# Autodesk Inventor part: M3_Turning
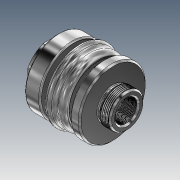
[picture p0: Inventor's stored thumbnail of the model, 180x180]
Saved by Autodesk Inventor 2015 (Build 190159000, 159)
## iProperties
Created: 2015-04
Part Number: M3_Turning
Material: Alumínio 6061
Document SubType Name: Modeling
Designer: Andrew Almeida
Density: 2.7 g/cm^3
Appearance: Alumínio - Plano
Title: C:/Users/Andrew Almeida/Documents/Projeto WS2015/WS2015 CAD Data ANLAS/06/#06 - CNC Turning/01 - 3D Models/M3_Turning.stp
Creation Date: 2015-04-23
Sending System: Autodesk Translation Framework v4.0.0.5211
Preprocessor: ST-DEVELOPER v16.1
Author: Andrew Almeida
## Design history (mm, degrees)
node "M3_Turning1"
feature "Rosca1" dims "d0" = 10, "d1" = 0
feature "Rosca2" dims "d2" = 10, "d3" = 0
sketch "Esboço2"
  geometry: L1 (23, 0)-(23, 12); L2 (23, 12)-(21.517, 12); L3 (21.517, 12)-(21.517, 0); L4 (21.517, 0)-(23, 0); L5 (0, -22.217)-(0, 118.036) reference
  constraints: 8 end point
revolve "Revolução1" sketch "Esboço2" stored, may be unused: angle "d13" = 0 deg
sketch "Esboço3"
  geometry: L1 (23, 0)-(23, 12); L2 (23, 12)-(21.517, 12); L3 (21.517, 12)-(21.517, 0); L4 (21.517, 0)-(23, 0); L5 (0, -22.217)-(0, 118.036) reference
  constraints: 8 end point
revolve "Revolução2" sketch "Esboço3" stored, may be unused: angle "d14" = 0 deg
sketch "Esboço1"
  geometry: L1 (-1.167, -21.618)-(-1, -21.618); L2 (0.167, -22.899)-(0, -23.219); L3 (-2, -23.219)-(-2.167, -22.899); L4 (-0.833, -21.618)-(-1, -21.298); L5 (-1, -21.298)-(-1.167, -21.618); L6 (-2, -23.219)-(-1.833, -22.899); L7 (-0.833, -21.618)-(-0.167, -22.899); L8 (-2.167, -22.899)-(-1.833, -22.899); L9 (0.167, -22.899)-(-0.167, -22.899); L10 (-2, -23.219)-(-2, -22.899); L11 (0, -23.219)-(0, -22.899); L12 (-1, -21.298)-(-1, -21.517); L13 (-2, -23)-(0, -23); L14 (-0.167, -22.899)-(0, -23.219); L15 (-1.833, -22.899)-(-1.167, -21.618); L16 (0, 0)-(0, 0.018); L17 (0, 0.018)-(0, 0); L18 (0, 0)-(0.033, 0); L19 (-1, -21.517)-(-1, -21.618); L20 (-1, -21.618)-(-0.833, -21.618); A1 r 0.188 centre (-2, -22.812) between (-2.167, -22.899) and (-2, -23); A2 r 0.188 centre (-2, -22.812) between (-2, -23) and (-1.833, -22.899); A3 r 0.188 centre (0, -22.812) between (-0.167, -22.899) and (0, -23); A4 r 0.188 centre (0, -22.812) between (0, -23) and (0.167, -22.899); A5 r 0.188 centre (-1, -21.705) between (-1, -21.517) and (-1.167, -21.618); A6 r 0.188 centre (-1, -21.705) between (-0.833, -21.618) and (-1, -21.517)
  constraints: 40 end point, 12 point on circle, 10 parallel, 8 tangent, 6 centre point, 6 collinear, 2 midpoint, 2 point on line, 1 horizontal, 1 perpendicular, 3 other
  dimensions: "d4" = 55 deg angle of L7 L15 (= d11); "d5" = 0.32017 distance of L4.end L1.end (= 0.160083 x Esboço1_Pitch); "d6" = 0.32017 distance of L2.end L11.end (= 0.160083 x Esboço1_Pitch); "Esboço1_ThreadOffset" = 0 distance between parallel lines of L16 L11; "Esboço1_MajorRadius" = 23 distance from line of L13 L16.start; "d9" = 2 distance from line of L2.end L10 (= Esboço1_Pitch); "Esboço1_MinorRadius" = 21.51708 distance edge to line of A6 L18 (derived)
feature "Espiral1" sketch "Esboço1" pitch "d15" = 2.002; turns "d17" = 1; dims "d16" = 16, "d18" = 0, angle "d19" = 0 deg, angle "d20" = 0 deg, "d21" = 0, "d22" = 0
sketch "Esboço5"
  geometry: L1 (15, 0)-(15, 18); L2 (15, 18)-(14.259, 18); L3 (14.259, 18)-(14.259, 0); L4 (14.259, 0)-(15, 0); L5 (0, -22)-(0, 118) reference
  constraints: 8 end point
revolve "Revolução3" sketch "Esboço5" stored, may be unused: angle "d32" = 0 deg
sketch "Esboço4"
  geometry: L1 (-0.583, -0.051)-(-0.5, -0.051); L2 (0.083, -0.691)-(0, -0.851); L3 (-1, -0.851)-(-1.083, -0.691); L4 (-0.417, -0.051)-(-0.5, 0.109); L5 (-0.5, 0.109)-(-0.583, -0.051); L6 (-1, -0.851)-(-0.917, -0.691); L7 (-0.417, -0.051)-(-0.083, -0.691); L8 (-1.083, -0.691)-(-0.917, -0.691); L9 (0.083, -0.691)-(-0.083, -0.691); L10 (-1, -0.851)-(-1, -0.691); L11 (0, -0.851)-(0, -0.691); L12 (-0.5, 0.109)-(-0.5, 0); L13 (-1, -0.742)-(0, -0.742); L14 (-0.083, -0.691)-(0, -0.851); L15 (-0.917, -0.691)-(-0.583, -0.051); L16 (0, 0)-(0, 0.018); L17 (0, 0.018)-(0, 0); L18 (0, 0)-(0.033, 0); L19 (-0.5, 0)-(-0.5, -0.051); L20 (-0.5, -0.051)-(-0.417, -0.051); A1 r 0.094 centre (-1, -0.648) between (-1.083, -0.691) and (-1, -0.742); A2 r 0.094 centre (-1, -0.648) between (-1, -0.742) and (-0.917, -0.691); A3 r 0.094 centre (0, -0.648) between (-0.083, -0.691) and (0, -0.742); A4 r 0.094 centre (0, -0.648) between (0, -0.742) and (0.083, -0.691); A5 r 0.094 centre (-0.5, -0.094) between (-0.5, 0) and (-0.583, -0.051); A6 r 0.094 centre (-0.5, -0.094) between (-0.417, -0.051) and (-0.5, 0)
  constraints: 40 end point, 12 point on circle, 10 parallel, 8 tangent, 6 centre point, 6 collinear, 2 midpoint, 2 point on line, 1 horizontal, 1 perpendicular, 3 other
  dimensions: "d23" = 55 deg angle of L7 L15 (= d30); "d24" = 0.16008 distance of L4.end L1.end (= 0.160083 x Esboço4_Pitch); "d25" = 0.16008 distance of L2.end L11.end (= 0.160083 x Esboço4_Pitch); "Esboço4_ThreadOffset" = 0 distance between parallel lines of L16 L11; "Esboço4_MajorRadius" = 0.74146 distance from line of L13 L16.start; "d28" = 1 distance from line of L2.end L10 (= Esboço4_Pitch); "Esboço4_MinorRadius" = 0 distance edge to line of A6 L18 (derived)
feature "Espiral2" sketch "Esboço4" pitch "d33" = 1.5015; turns "d35" = 1; dims "d34" = 20.99995, "d36" = 0, angle "d37" = 0 deg, angle "d38" = 0 deg, "d39" = 0, "d40" = 0
node "Body1"
node "Base1"
node "Sólido2"
node "Sólido3"
other parameters: "d11" = 55 deg [user parameter; used in 1 equation term], "Esboço1_Pitch" = 2 [user parameter; used in 3 equation terms], "d30" = 55 deg [user parameter; used in 1 equation term], "Esboço4_Pitch" = 1 [user parameter; used in 3 equation terms]
